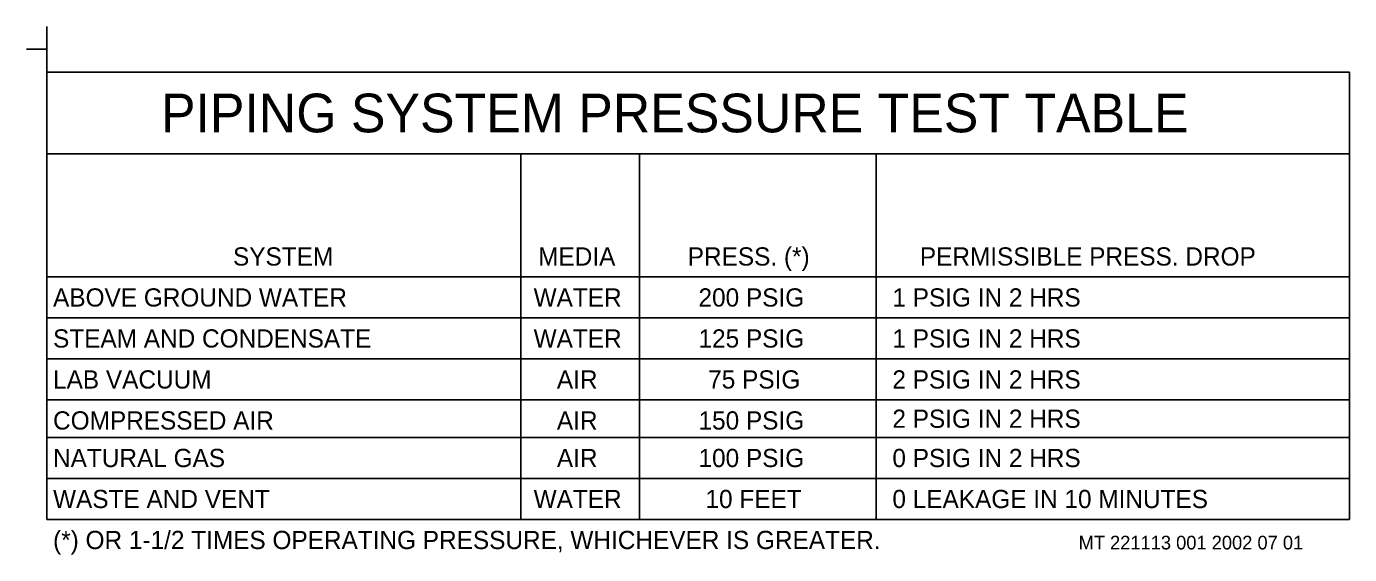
# Model space of a CAD drawing. Extents: x 10068.6 to 10117, y 10112.5 to 10131.9.
import ezdxf

# ---------------------------------------------------------------- set-up
doc = ezdxf.new("R2010")
doc.units = 0
for name, color, linetype in [('G-SCHD-HTXT', 7, 'Continuous'), ('G-SCHD-LINE', 7, 'Continuous'), ('G-SCHD-TEXT', 7, 'Continuous'), ('G-SCHD-TTXT', 7, 'Continuous')]:
    doc.layers.add(name, color=color, linetype=linetype)

msp = doc.modelspace()

# ---------------------------------------------------------------- linework, layer by layer
at = {"layer": 'G-SCHD-LINE'}
for p, q in [((10069.356, 10130.206), (10069.356, 10131.873)), ((10069.356, 10131.04), (10068.606, 10131.04)), ((10069.356, 10130.206), (10116.998, 10130.206)), ((10069.356, 10130.206), (10069.356, 10122.706)), ((10116.998, 10130.206), (10116.998, 10122.706)), ((10069.356, 10127.206), (10116.998, 10127.206)), ((10086.689, 10127.206), (10086.689, 10122.706)), ((10091.023, 10127.206), (10091.023, 10122.706)), ((10099.689, 10127.206), (10099.689, 10122.706)), ((10069.356, 10122.706), (10073.689, 10122.706)), ((10069.356, 10122.706), (10069.356, 10113.833)), ((10073.689, 10122.706), (10073.689, 10122.706)), ((10073.689, 10122.706), (10078.023, 10122.706)), ((10078.023, 10122.706), (10078.023, 10122.706)), ((10078.023, 10122.706), (10082.356, 10122.706)), ((10082.356, 10122.706), (10086.689, 10122.706)), ((10086.689, 10122.706), (10086.689, 10122.706)), ((10086.689, 10122.706), (10091.023, 10122.706)), ((10086.689, 10122.706), (10086.689, 10113.833)), ((10091.023, 10122.706), (10091.023, 10122.706)), ((10091.023, 10122.706), (10095.356, 10122.706)), ((10091.023, 10122.706), (10091.023, 10113.833)), ((10095.356, 10122.706), (10095.356, 10122.706)), ((10095.356, 10122.706), (10099.689, 10122.706)), ((10099.689, 10122.706), (10099.689, 10122.706)), ((10099.689, 10122.706), (10104.023, 10122.706)), ((10099.689, 10122.706), (10099.689, 10113.833)), ((10104.023, 10122.706), (10104.023, 10122.706)), ((10104.023, 10122.706), (10108.356, 10122.706)), ((10108.356, 10122.706), (10108.356, 10122.706)), ((10108.356, 10122.706), (10112.689, 10122.706)), ((10112.689, 10122.706), (10112.689, 10122.706)), ((10112.689, 10122.706), (10112.689, 10122.706)), ((10112.689, 10122.706), (10116.998, 10122.706)), ((10116.998, 10122.706), (10116.998, 10113.833)), ((10069.356, 10121.206), (10116.998, 10121.206)), ((10069.356, 10119.706), (10116.998, 10119.706)), ((10069.356, 10118.206), (10116.998, 10118.206)), ((10069.356, 10116.833), (10116.998, 10116.833)), ((10069.356, 10115.333), (10116.998, 10115.333)), ((10069.356, 10113.833), (10116.998, 10113.833))]:
    msp.add_line(p, q, dxfattribs=at)

# ---------------------------------------------------------------- texts
at = {"layer": 'G-SCHD-HTXT'}
for s, height, p in [('SYSTEM', 0.6667, (10076.161, 10123.123)), ('MEDIA', 0.6667, (10087.322, 10123.123)), ('PRESS. (*)', 0.6667, (10092.793, 10123.123)), ('PERMISSIBLE PRESS. DROP', 0.66667, (10101.283, 10123.123)), ('WATER', 0.6667, (10087.156, 10121.623)), ('200 PSIG', 0.6667, (10093.186, 10121.623)), ('WATER', 0.6667, (10087.156, 10120.123)), ('125 PSIG', 0.6667, (10093.186, 10120.123)), ('AIR', 0.6667, (10088.006, 10118.623)), (' 75 PSIG', 0.6667, (10093.293, 10118.623)), ('AIR', 0.6667, (10088.006, 10117.123)), ('150 PSIG', 0.6667, (10093.186, 10117.123)), ('AIR', 0.6667, (10088.006, 10115.749)), ('100 PSIG', 0.6667, (10093.186, 10115.749)), ('WATER', 0.6667, (10087.156, 10114.249)), ('10 FEET', 0.6667, (10093.441, 10114.249)), ('MT 221113 001 2002 07 01', 0.5, (10107.087, 10112.736))]:
    msp.add_text(s, height=height, dxfattribs=at).set_placement(p)
at = {"layer": 'G-SCHD-TEXT'}
for s, height, p in [('ABOVE GROUND WATER', 0.66667, (10069.579, 10121.623)), ('1 PSIG IN 2 HRS', 0.66667, (10100.278, 10121.623)), ('STEAM AND CONDENSATE', 0.66667, (10069.579, 10120.123)), ('1 PSIG IN 2 HRS', 0.66667, (10100.278, 10120.123)), ('LAB VACUUM', 0.6667, (10069.579, 10118.623)), ('2 PSIG IN 2 HRS', 0.66667, (10100.278, 10118.623)), ('2 PSIG IN 2 HRS', 0.66667, (10100.278, 10117.186)), ('COMPRESSED AIR', 0.66667, (10069.579, 10117.123)), ('NATURAL GAS', 0.66667, (10069.579, 10115.749)), ('0 PSIG IN 2 HRS', 0.66667, (10100.278, 10115.749)), ('WASTE AND VENT', 0.66667, (10069.579, 10114.249)), ('0 LEAKAGE IN 10 MINUTES', 0.66667, (10100.278, 10114.249)), ('(*) OR 1-1/2 TIMES OPERATING PRESSURE, WHICHEVER IS GREATER.', 0.66667, (10069.579, 10112.749))]:
    msp.add_text(s, height=height, dxfattribs=at).set_placement(p)
at = {"layer": 'G-SCHD-TTXT'}
msp.add_text('PIPING SYSTEM PRESSURE TEST TABLE', height=1.41667, dxfattribs=at).set_placement((10073.526, 10127.998))

doc.saveas('drawing.dxf')
